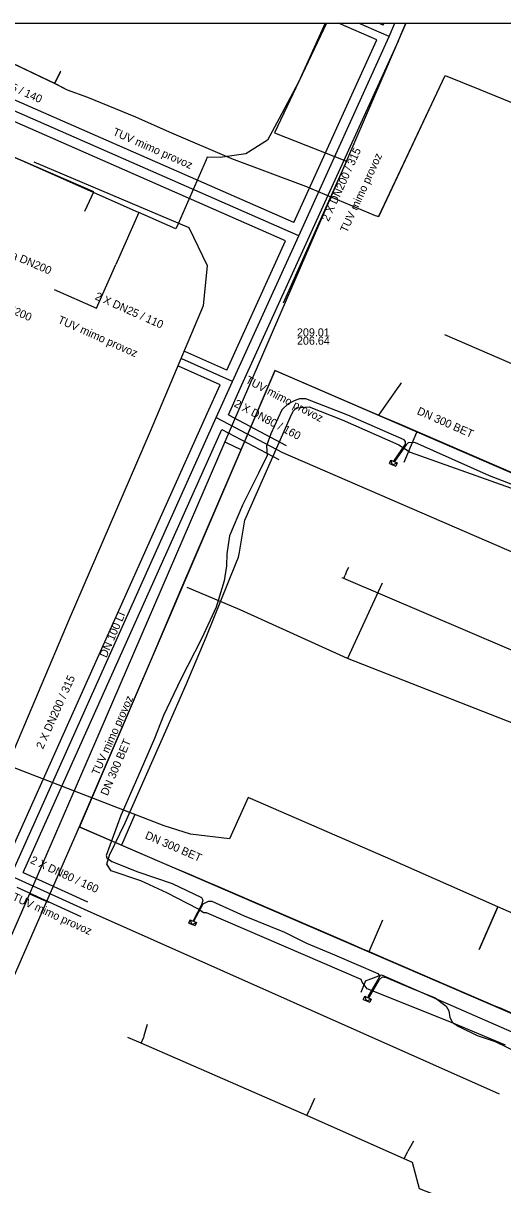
# Model space of a CAD drawing. Extents: x -596024 to -594475, y -1163820 to -1161957.
# Drawn here: x -595789 to -595741.1, y -1162073 to -1161956.9 of the extents above; entities that cross this region are included whole.
import ezdxf

# ---------------------------------------------------------------- set-up
doc = ezdxf.new("R2010")
doc.units = 0
for name, color, linetype in [('31', 7, 'Continuous'), ('Level 1', 7, 'Continuous'), ('Vrstva 12', 7, 'Continuous'), ('Vrstva 13', 7, 'Continuous'), ('Vrstva 15', 7, 'Continuous'), ('Vrstva 16', 7, 'Continuous'), ('Vrstva 25', 7, 'Continuous'), ('Vrstva 37', 7, 'Continuous'), ('Vrstva 38', 7, 'Continuous'), ('Vrstva 41', 7, 'Continuous'), ('Vrstva 42', 7, 'Continuous'), ('Vrstva 43', 7, 'Continuous'), ('Vrstva 55', 7, 'Continuous'), ('Vrstva 63', 7, 'Continuous'), ('Vrstva 9', 7, 'Continuous')]:
    doc.layers.add(name, color=color, linetype=linetype)

# ---------------------------------------------------------------- blocks, each defined once
blk = doc.blocks.new('NN630')
at = {"layer": '31'}
for points in [[(-0.003, -0.7), (-0.703, 0)], [(-0.703, -0.7), (-0.703, 0), (0.697, 0), (0.697, -0.7)], [(-0.003, -0.7), (0.697, 0)], [(-0.703, -0.7), (0.697, -0.7)]]:
    blk.add_lwpolyline(points, dxfattribs=at)

msp = doc.modelspace()

# ---------------------------------------------------------------- linework, layer by layer
at = {"layer": 'Level 1'}
for points in [[(-595783.41, -1162037.21), (-595763.86, -1161991.59), (-595710.02, -1162014.9)], [(-595751.29, -1161992.8), (-595751.43, -1161993.01), (-595751.69, -1161993.38), (-595753.54, -1161996.05)], [(-595750.99, -1162000.74), (-595749.73, -1161997.74)], [(-595767.36, -1162015.5), (-595772.66, -1162013.26)], [(-595753.2, -1162012.83), (-595756.65, -1162020.36)], [(-595729.38, -1162023.14), (-595731.34, -1162027.05), (-595735.92, -1162028.48), (-595756.65, -1162020.36), (-595767.36, -1162015.5)], [(-595777.9, -1162035.94), (-595779.22, -1162039.01)], [(-595729.72, -1162060.4), (-595783.41, -1162037.21)], [(-595753.16, -1162046.52), (-595754.52, -1162049.68)]]:
    msp.add_lwpolyline(points, dxfattribs=at)
at = {"layer": 'Vrstva 12'}
for points in [[(-595758.866, -1161956.88), (-595761.54, -1161962.78), (-595763.47, -1161966.39), (-595764.65, -1161968.57), (-595766.8, -1161969.93), (-595769.37, -1161970.3), (-595770.66, -1161970.26), (-595770.78, -1161970.52), (-595773.58, -1161976.93), (-595773.8, -1161977.43), (-595777.48, -1161975.8)], [(-595793.71, -1161959.18), (-595785.89, -1161962.89)], [(-595785.89, -1161962.89), (-595785.33, -1161961.73)], [(-595785.89, -1161962.89), (-595784.66, -1161963.55), (-595782.62, -1161964.26), (-595777.84, -1161966.24), (-595774.46, -1161967.74), (-595768.25, -1161970.39), (-595760.86, -1161973.15), (-595753.9, -1161976.08), (-595753.52, -1161976.18), (-595746.89, -1161962.09), (-595743.43, -1161963.5), (-595735.03, -1161966.94), (-595733.9, -1161966.99), (-595707.89, -1161978.27), (-595695.95, -1161983.52), (-595693.23, -1161984.78), (-595692.61, -1161985.26)], [(-595799.96, -1161966.5), (-595798.86, -1161966.3), (-595777.48, -1161975.8)], [(-595782.88, -1161975.65), (-595781.98, -1161973.73), (-595797.6, -1161966.96)], [(-595777.48, -1161975.8), (-595778.12, -1161977.23)], [(-595778.12, -1161977.23), (-595779.8, -1161981)], [(-595785.95, -1161983.49), (-595781.73, -1161985.36), (-595779.8, -1161981)]]:
    msp.add_lwpolyline(points, dxfattribs=at)
at = {"layer": 'Vrstva 13'}
for points in [[(-595750.816, -1161956.88), (-595756.662, -1161970.404), (-595768.903, -1161998.725), (-595781.505, -1162027.885), (-595788.416, -1162043.868), (-595805.78, -1162083.59)], [(-595768.903, -1161998.725), (-595768.76, -1161998.79), (-595767.293, -1161999.488)], [(-595788.416, -1162043.868), (-595788.13, -1162044), (-595786.518, -1162044.729)]]:
    msp.add_lwpolyline(points, dxfattribs=at)
at = {"layer": 'Vrstva 16'}
for points in [[(-595712.71, -1162035.16), (-595713.43, -1162034.85), (-595713.97, -1162034.59), (-595714.167, -1162034.504), (-595714.563, -1162034.332), (-595717.44, -1162033.08), (-595726.83, -1162029.55), (-595729.22, -1162024.32), (-595730.59, -1162023.67), (-595739.993, -1162019.643), (-595740.49, -1162019.43), (-595757.02, -1162012.37), (-595757.17, -1162012.3)], [(-595757.02, -1162012.37), (-595756.89, -1162012.04)], [(-595756.56, -1162011.27), (-595756.74, -1162011.65), (-595756.89, -1162012.04)], [(-595776.66, -1162056.93), (-595776.99, -1162058.09), (-595777.04, -1162058.29)], [(-595742.01, -1162080.26), (-595742.09, -1162078.7), (-595742.23, -1162076.19), (-595749.45, -1162073.38), (-595750.16, -1162070.73), (-595750.99, -1162070.37), (-595760.72, -1162066.02), (-595777.25, -1162058.79), (-595778.6, -1162058.25)], [(-595777.25, -1162058.79), (-595777.04, -1162058.29)], [(-595759.942, -1162064.325), (-595760.36, -1162065.22), (-595760.48, -1162065.53)], [(-595760.72, -1162066.02), (-595760.48, -1162065.53)], [(-595750.06, -1162068.59), (-595750.5, -1162069.35), (-595750.62, -1162069.59)], [(-595750.99, -1162070.37), (-595750.62, -1162069.59)]]:
    msp.add_lwpolyline(points, dxfattribs=at)
at = {"layer": 'Vrstva 25'}
for p, q in [((-595793.711, -1161959.178), (-595785.798, -1161962.933)), ((-595785.905, -1161962.908), (-595785.293, -1161961.652)), ((-595753.519, -1161976.177), (-595746.888, -1161962.088)), ((-595746.888, -1161962.088), (-595743.434, -1161963.501)), ((-595785.798, -1161962.933), (-595784.664, -1161963.549)), ((-595784.664, -1161963.549), (-595782.616, -1161964.257)), ((-595743.434, -1161963.501), (-595735.034, -1161966.944)), ((-595782.616, -1161964.257), (-595777.837, -1161966.236)), ((-595781.979, -1161973.731), (-595797.602, -1161966.963)), ((-595777.837, -1161966.236), (-595774.457, -1161967.737)), ((-595774.457, -1161967.737), (-595768.247, -1161970.388)), ((-595768.247, -1161970.388), (-595760.858, -1161973.153)), ((-595782.828, -1161975.535), (-595781.979, -1161973.731)), ((-595760.858, -1161973.153), (-595753.896, -1161976.081)), ((-595753.896, -1161976.081), (-595753.519, -1161976.177)), ((-595754.845, -1162052.575), (-595755.318, -1162053.746)), ((-595754.845, -1162052.575), (-595753.247, -1162051.994)), ((-595753.247, -1162051.994), (-595740.222, -1162057.667))]:
    msp.add_line(p, q, dxfattribs=at)
msp.add_lwpolyline([(-595795.101, -1161958.666), (-595793.711, -1161959.178), (-595785.798, -1161962.933), (-595784.664, -1161963.549), (-595782.616, -1161964.257), (-595777.837, -1161966.236), (-595774.457, -1161967.737), (-595768.247, -1161970.388), (-595760.858, -1161973.153), (-595753.896, -1161976.081), (-595753.519, -1161976.177), (-595746.888, -1161962.088), (-595743.434, -1161963.501), (-595735.034, -1161966.944), (-595733.897, -1161966.99), (-595707.889, -1161978.267), (-595695.948, -1161983.519), (-595693.233, -1161984.785), (-595692.606, -1161985.262)], dxfattribs=at)
at = {"layer": 'Vrstva 37'}
for p, q in [((-595761.518, -1161978.116), (-595809.858, -1161956.88)), ((-595752.475, -1161958.211), (-595755.551, -1161956.88)), ((-595752.475, -1161958.211), (-595751.907, -1161956.88)), ((-595761.518, -1161978.116), (-595752.475, -1161958.211)), ((-595768.137, -1161992.684), (-595761.518, -1161978.116)), ((-595768.137, -1161992.684), (-595773.212, -1161990.428)), ((-595769.754, -1161996.289), (-595768.137, -1161992.684)), ((-595769.754, -1161996.289), (-595763.134, -1161999.771)), ((-595763.134, -1161999.771), (-595719.267, -1162018.835)), ((-595790.27, -1162042.079), (-595782.949, -1162045.418)), ((-595782.949, -1162045.418), (-595741.492, -1162063.88))]:
    msp.add_line(p, q, dxfattribs=at)
msp.add_lwpolyline([(-595790.27, -1162042.079), (-595774.86, -1162007.644), (-595769.754, -1161996.289)], dxfattribs=at)
at = {"layer": 'Vrstva 38'}
for p, q in [((-595762.847, -1161978.625), (-595812.344, -1161956.88)), ((-595762.02, -1161976.803), (-595807.372, -1161956.88)), ((-595753.724, -1161958.542), (-595757.565, -1161956.88)), ((-595753.079, -1161957.078), (-595753.537, -1161956.88)), ((-595753.079, -1161957.078), (-595752.994, -1161956.88)), ((-595751.555, -1161958.604), (-595750.819, -1161956.88)), ((-595762.02, -1161976.803), (-595753.724, -1161958.542)), ((-595760.608, -1161978.53), (-595751.565, -1161958.625)), ((-595768.72, -1161991.55), (-595762.847, -1161978.625)), ((-595767.227, -1161993.098), (-595760.608, -1161978.53)), ((-595768.72, -1161991.55), (-595772.887, -1161989.697)), ((-595769.378, -1161993.008), (-595773.537, -1161991.159)), ((-595770.666, -1161995.88), (-595769.378, -1161993.008)), ((-595768.54, -1161996.024), (-595767.225, -1161993.093)), ((-595768.54, -1161996.024), (-595762.762, -1161999.063)), ((-595769.196, -1161997.486), (-595763.506, -1162000.479)), ((-595789.033, -1162041.764), (-595782.617, -1162044.69)), ((-595789.697, -1162043.22), (-595783.281, -1162046.146))]:
    msp.add_line(p, q, dxfattribs=at)
for points in [[(-595791.183, -1162041.671), (-595775.772, -1162007.235), (-595770.666, -1161995.879)], [(-595789.033, -1162041.764), (-595773.948, -1162008.053), (-595769.196, -1161997.486)]]:
    msp.add_lwpolyline(points, dxfattribs=at)
at = {"layer": 'Vrstva 42'}
for points in [[(-595739.009, -1162003.434), (-595742.46, -1162002.12), (-595749.91, -1161998.79), (-595750.59, -1161998.8), (-595750.789, -1161999), (-595751.96, -1162000.67), (-595752.011, -1162000.691), (-595752.009, -1162000.639), (-595750.86, -1161998.93), (-595750.85, -1161998.69), (-595750.98, -1161998.52), (-595756.61, -1161996.05), (-595760.8, -1161994.43), (-595761.46, -1161994.43), (-595761.98, -1161994.63), (-595762.58, -1161994.92), (-595763.21, -1161995.51), (-595764.3, -1161997.92), (-595764.75, -1161999.12), (-595764.66, -1162000.08), (-595765.55, -1162001.83), (-595767.13, -1162005.05), (-595768.45, -1162008.09), (-595768.72, -1162009.92), (-595768.74, -1162011.1), (-595768.98, -1162012.61), (-595769.78, -1162015.24), (-595771.19, -1162018.34), (-595773.31, -1162022.43), (-595775.02, -1162026.07), (-595775.92, -1162028.36), (-595777.58, -1162032.19), (-595779.28, -1162036.06), (-595780.76, -1162040.04), (-595780.69, -1162040.29), (-595780.18, -1162040.64), (-595777.6, -1162041.7), (-595774.17, -1162042.84), (-595771.23, -1162044.25), (-595771.1, -1162044.52), (-595771.22, -1162044.97), (-595772.043, -1162046.502), (-595772.044, -1162046.609), (-595771.964, -1162046.552), (-595771.07, -1162044.88), (-595770.54, -1162044.63), (-595770.21, -1162044.62), (-595766.96, -1162046.08), (-595762.95, -1162047.71), (-595760.74, -1162048.8), (-595757.94, -1162049.98), (-595753.63, -1162051.85), (-595753.43, -1162052.1), (-595753.58, -1162052.42), (-595754.59, -1162054.105), (-595754.61, -1162054.256), (-595754.467, -1162054.172), (-595753.46, -1162052.43), (-595753.15, -1162052.18), (-595752.78, -1162052.23), (-595750.37, -1162053.28), (-595747.9, -1162054.26), (-595746.78, -1162055.12), (-595746.53, -1162055.56), (-595746.42, -1162056.25), (-595746.16, -1162056.75), (-595745.53, -1162057.14), (-595743.69, -1162058.04), (-595741.89, -1162058.63), (-595738.66, -1162060.19)], [(-595740.86, -1162059.02), (-595746.25, -1162056.74), (-595754.67, -1162053.38), (-595755.17, -1162052.71), (-595755.28, -1162052.45), (-595757.22, -1162051.6), (-595770.75, -1162045.77), (-595771.04, -1162045.77), (-595771.54, -1162045.41), (-595774.71, -1162043.78), (-595777.29, -1162042.57), (-595780.25, -1162041.57), (-595780.7, -1162040.91), (-595780.42, -1162040.01), (-595778.86, -1162036.8), (-595774.66, -1162027.31), (-595772.75, -1162022.98), (-595770.78, -1162018.24), (-595767.77, -1162010.81), (-595767.532, -1162010.223), (-595767.45, -1162009.75), (-595766.89, -1162006.53), (-595762.33, -1161996.23), (-595762.09, -1161995.64), (-595761.734, -1161995.3), (-595760.47, -1161995.21), (-595757.19, -1161996.52), (-595751.52, -1161999.01), (-595750.4, -1161999.76), (-595736.82, -1162004.58)]]:
    msp.add_lwpolyline(points, dxfattribs=at)
at = {"layer": 'Vrstva 55'}
for points in [[(-595758.757, -1161956.88), (-595763.95, -1161967.83), (-595756.746, -1161970.678), (-595763.06, -1161984.86)], [(-595791.13, -1162030.83), (-595790.615, -1162031.043), (-595784.41, -1162016.39), (-595776.34, -1161997.66), (-595771.04, -1161985.08), (-595770.62, -1161981.12), (-595772.47, -1161977.34), (-595787.96, -1161970.78)], [(-595705.418, -1162013.322), (-595705.747, -1162013.284), (-595702.818, -1162006.146), (-595721.62, -1161998.99), (-595746.928, -1161988.013)], [(-595768.43, -1162038.38), (-595772.34, -1162037.92), (-595774.98, -1162037.09), (-595791.13, -1162030.83)], [(-595724.51, -1162058.37), (-595724, -1162055.71), (-595723.325, -1162054.043), (-595724.7, -1162053.49), (-595725.52, -1162053.14), (-595726.53, -1162052.63), (-595727.55, -1162051.41), (-595728.54, -1162050.92), (-595741.63, -1162045.19), (-595743.51, -1162049.44), (-595741.63, -1162045.19), (-595752.87, -1162040.21), (-595766.56, -1162034.27), (-595768.43, -1162038.38)]]:
    msp.add_lwpolyline(points, dxfattribs=at)
at = {"layer": 'Vrstva 63'}
msp.add_lwpolyline([(-594475.47, -1163820.23), (-596024.42, -1163820.23), (-596024.42, -1161956.88), (-594475.47, -1161956.88)], close=True, dxfattribs=at)
at = {"layer": 'Vrstva 9'}
for points in [[(-595763.9, -1161991.57), (-595767.074, -1161998.979), (-595773.218, -1162013.318), (-595776.305, -1162020.524), (-595783.45, -1162037.2)], [(-595710.01, -1162014.88), (-595751.592, -1161996.894), (-595752.96, -1161996.302), (-595755.043, -1161995.401), (-595763.9, -1161991.57)], [(-595783.45, -1162037.2), (-595788.212, -1162048.095), (-595791.304, -1162055.168), (-595803.14, -1162082.245), (-595804.481, -1162085.312)], [(-595729.69, -1162060.36), (-595739.278, -1162056.229), (-595741.381, -1162055.323), (-595741.822, -1162055.133), (-595752.788, -1162050.409), (-595754.377, -1162049.725), (-595755.286, -1162049.333), (-595756.324, -1162048.886), (-595769.842, -1162043.063), (-595769.843, -1162043.063), (-595770.403, -1162042.821), (-595772.414, -1162041.955), (-595774.159, -1162041.203), (-595779.844, -1162038.754), (-595783.45, -1162037.2)]]:
    msp.add_lwpolyline(points, dxfattribs=at)

# ---------------------------------------------------------------- block references
at = {"layer": 'Vrstva 43', "xscale": 0.5}
for p, yscale, rotation in [((-595752.011, -1162000.691), 0.5000000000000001, -22.00000000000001), ((-595772.044, -1162046.609), 0.5000000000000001, -22.00000000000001), ((-595754.61, -1162054.256), 0.5, -23.999999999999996)]:
    msp.add_blockref('NN630', p, dxfattribs=dict(at, yscale=yscale, rotation=rotation))

# ---------------------------------------------------------------- texts
at = {"layer": 'Vrstva 12'}
for s, rotation, p in [('Kamenina DN200', 336.67488, (-595794.183, -1161978.67)), ('Kamenina DN200', 336.67488, (-595796.158, -1161983.333)), ('DN 300 BET', 336.26893, (-595749.774, -1161995.921)), ('DN 300 BET', 66.80688, (-595780.624, -1162034.146)), ('DN 300 BET', 336.67, (-595776.939, -1162038.322))]:
    msp.add_text(s, height=0.8, rotation=rotation, dxfattribs=at).set_placement(p)
for s, p in [('209.01', (-595761.695, -1161988.174)), ('206.64', (-595761.695, -1161989.006))]:
    msp.add_text(s, height=0.8, dxfattribs=at).set_placement(p)
at = {"layer": 'Vrstva 15'}
msp.add_text('DN 100 LI', height=0.8, rotation=66.63499, dxfattribs=at).set_placement((-595780.728, -1162020.345))
at = {"layer": 'Vrstva 41'}
for s, rotation, p in [('2 X DN65 / 140', 336.26893, (-595794.068, -1161961.934)), ('TUV mimo provoz', 336.26893, (-595780.172, -1161968.025)), ('2 X DN200 / 315', 65.54637, (-595758.544, -1161976.752)), ('TUV mimo provoz', 65.54637, (-595756.708, -1161977.873)), ('2 X DN25 / 110', 336.03973, (-595781.946, -1161984.443)), ('TUV mimo provoz', 336.03973, (-595785.658, -1161986.799)), ('TUV mimo provoz', 332.25821, (-595766.913, -1161992.78)), ('2 X DN80 / 160', 332.25821, (-595768.058, -1161995.14)), ('2 X DN200 / 315', 65.89014, (-595787.068, -1162029.481)), ('TUV mimo provoz', 65.89014, (-595781.517, -1162032.108)), ('2 X DN80 / 160', 335.46679, (-595788.395, -1162040.787)), ('TUV mimo provoz', 335.46679, (-595790.197, -1162044.47))]:
    msp.add_text(s, height=0.8, rotation=rotation, dxfattribs=at).set_placement(p)

doc.saveas('drawing.dxf')
